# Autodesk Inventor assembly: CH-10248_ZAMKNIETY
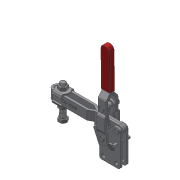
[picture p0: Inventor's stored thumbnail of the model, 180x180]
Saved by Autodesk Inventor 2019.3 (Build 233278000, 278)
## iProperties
Company: Î¢ÈíÖÐ¹ú
Created: 2012-09
Part Number: CH-10248_ZAMKNIETY
Material: Ogólny
Description: STEP AP203
Document SubType Name: Assembly
Designer: CADENGINEERING4
Sending System: SolidWorks 2010
Preprocessor: SwSTEP 2.0
Title: CH-10248.STEP
Author: Î¢ÈíÓÃ»§
Revision Number: ÈÎºÎ
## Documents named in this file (18)
- D:\Vault_2016\Projekty\NASZ KATALOG\CLAMPTEK\STRONA\Vertical toggle clamp\CH-10248\CH-10248_ZAMKNIETY.iam
- D:\Vault_2016\Projekty\NASZ KATALOG\CLAMPTEK\STEP FILES\Vertical toggle clamp\CH-10248\CH-10247-09.ipt
- D:\Vault_2016\Projekty\NASZ KATALOG\CLAMPTEK\STEP FILES\Vertical toggle clamp\CH-10248\CH-FW-120.ipt
- D:\Vault_2016\Projekty\NASZ KATALOG\CLAMPTEK\STEP FILES\Vertical toggle clamp\CH-10248\CH-10248-01 STRAIGHT BASE.ipt
- D:\Vault_2016\Projekty\NASZ KATALOG\CLAMPTEK\STEP FILES\Vertical toggle clamp\CH-10248\CH-10247-10.ipt
- D:\Vault_2016\Projekty\NASZ KATALOG\CLAMPTEK\STEP FILES\Vertical toggle clamp\CH-10248\CH-10247-08.ipt
- D:\Vault_2016\Projekty\NASZ KATALOG\CLAMPTEK\STEP FILES\Vertical toggle clamp\CH-10248\CH-10247-06.ipt
- D:\Vault_2016\Projekty\NASZ KATALOG\CLAMPTEK\STEP FILES\Vertical toggle clamp\CH-10248\CH-10247-03 HANDLE.ipt
- D:\Vault_2016\Projekty\NASZ KATALOG\CLAMPTEK\STEP FILES\Vertical toggle clamp\CH-10248\CH-10247-04 CONNECTING-PLATE.ipt
- D:\Vault_2016\Projekty\NASZ KATALOG\CLAMPTEK\STEP FILES\Vertical toggle clamp\CH-10248\3-8-16 LOCK NUT.ipt
- D:\Vault_2016\Projekty\NASZ KATALOG\CLAMPTEK\STEP FILES\Vertical toggle clamp\CH-10248\CH-10247-11.ipt
- D:\Vault_2016\Projekty\NASZ KATALOG\CLAMPTEK\STEP FILES\Vertical toggle clamp\CH-10248\CH-10247-07.ipt
- D:\Vault_2016\Projekty\NASZ KATALOG\CLAMPTEK\STEP FILES\Vertical toggle clamp\CH-10248\CH-10248-02 U-BAR.ipt
- D:\Vault_2016\Projekty\NASZ KATALOG\CLAMPTEK\STEP FILES\Vertical toggle clamp\CH-10248\CH-SA-12300 SPINDLE SUPPLIED.ipt
- D:\Vault_2016\Projekty\NASZ KATALOG\CLAMPTEK\STEP FILES\Vertical toggle clamp\CH-10248\CH-SA-12300 NUT.ipt
- D:\Vault_2016\Projekty\NASZ KATALOG\CLAMPTEK\STEP FILES\Vertical toggle clamp\CH-10248\M6X25.ipt
- D:\Vault_2016\Projekty\NASZ KATALOG\CLAMPTEK\STEP FILES\Vertical toggle clamp\CH-10248\M6 Nut.ipt
- D:\Vault_2016\Projekty\NASZ KATALOG\CLAMPTEK\STEP FILES\Vertical toggle clamp\CH-10248\CH-10247-05.ipt
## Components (23 placed, 23 different names)
1. CH-10247-09_1
2. CH-FW-120_2
3. CH-10248-01 STRAIGHT BASE_3
4. CH-10247-10_4
5. CH-10247-08_5
6. CH-10247-06_6
7. CH-10247-03 HANDLE_7
8. CH-10247-04 CONNECTING-PLATE_8
9. 3-8-16 LOCK NUT_9
10. CH-10247-11_10
11. CH-10247-07_11
12. CH-10248-02 U-BAR_12
13. CH-10247-08_13
14. CH-SA-12300 SPINDLE SUPPLIED_14
15. CH-SA-12300 NUT_15
16. CH-10247-06_16
17. CH-SA-12300 NUT_17
18. CH-FW-120_18
19. M6X25_19
20. CH-10247-11_20
21. 3-8-16 LOCK NUT_21
22. M6 Nut_22
23. CH-10247-05_23
